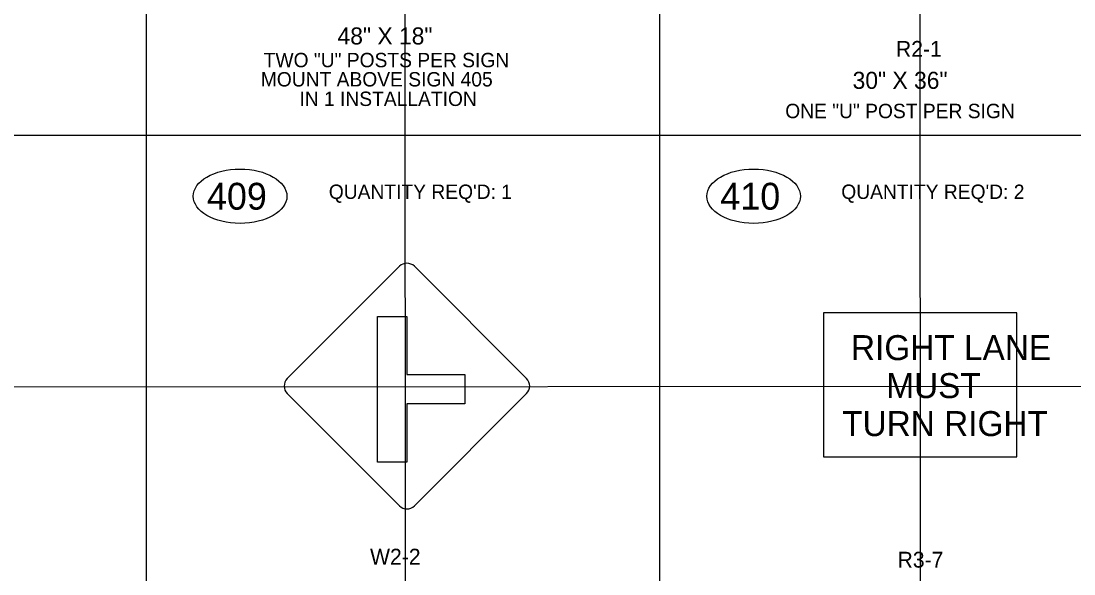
# Model space of a CAD drawing. Extents: x 1977705 to 1981198, y 827296 to 829291.
# Drawn here: x 1979879 to 1980318.3, y 828320.6 to 828551.2 of the extents above; entities that cross this region are included whole.
import ezdxf

# ---------------------------------------------------------------- set-up
doc = ezdxf.new("R2010")
doc.units = 0
doc.layers.add('Level 34', color=7, linetype='Continuous')
doc.layers.add('Level 7', color=7, linetype='Continuous')

msp = doc.modelspace()

# ---------------------------------------------------------------- linework, layer by layer
at = {"layer": 'Level 34'}
for p, q in [((1980039.8, 827664.08), (1980039.2, 828783.26)), ((1980254.68, 827664.19), (1980254.07, 828783.37)), ((1981001.97, 828399.12), (1979481.32, 828398.3))]:
    msp.add_line(p, q, dxfattribs=at)
at = {"layer": 'Level 7'}
for p, q in [((1980027.74, 828428.04), (1980039.89, 828428.04)), ((1980027.74, 828367.29), (1980027.74, 828428.04)), ((1980039.89, 828428.04), (1980039.89, 828403.74)), ((1980039.89, 828403.74), (1980064.19, 828403.74)), ((1980064.19, 828403.74), (1980064.19, 828391.59)), ((1980089.94, 828395.88), (1980043.1, 828349.04)), ((1980064.19, 828391.59), (1980039.89, 828391.59)), ((1980039.89, 828391.59), (1980039.89, 828367.29)), ((1980039.89, 828367.29), (1980027.74, 828367.29))]:
    msp.add_line(p, q, dxfattribs=at)
for points in [[(1979931.19, 828713.79), (1979931.19, 827664.02)], [(1980145.44, 828713.91), (1980145.44, 827664.13)], [(1979502.24, 828503.56), (1980814.64, 828503.56)], [(1979990.06, 828402.07), (1980036.91, 828448.92)], [(1980043.1, 828448.92), (1980089.94, 828402.07)], [(1980036.91, 828349.04), (1979990.06, 828395.88)]]:
    msp.add_lwpolyline(points, dxfattribs=at)
msp.add_lwpolyline([(1980213.78, 828429.46), (1980213.78, 828369.48), (1980294.5, 828369.48), (1980294.5, 828429.46)], close=True, dxfattribs=at)
for centre, start, end in [((1980040, 828445.82), 89.9935, 135), ((1980040, 828445.82), 44.987, 89.9935), ((1979993.16, 828398.98), 135, 225), ((1980086.85, 828398.98), 315, 45), ((1980040, 828352.13), 225, 270), ((1980040, 828352.13), 270, 315)]:
    msp.add_arc(centre, 4.38, start, end, dxfattribs=at)
for centre in [(1979970.39, 828478.14), (1980184.64, 828478.14)]:
    msp.add_ellipse(centre, major_axis=(-19.54, 0), ratio=0.580127, dxfattribs=at)

# ---------------------------------------------------------------- texts
for s, height, p in [('48" X 18"', 7.125, (1980011.05, 828541.42)), ('R2-1', 6.6, (1980244.02, 828536.28)), ('TWO "U" POSTS PER SIGN', 6, (1979980.24, 828531.93)), ('MOUNT ABOVE SIGN 405 ', 6, (1979979.03, 828523.91)), ('30" X 36"', 7.125, (1980225.95, 828522.92)), ('IN 1 INSTALLATION', 6, (1979995.14, 828515.78)), ('ONE "U" POST PER SIGN', 6, (1980197.84, 828510.69)), ("QUANTITY REQ'D: 1", 6, (1980007.4, 828477.01)), ("QUANTITY REQ'D: 2", 6, (1980221.22, 828477.01)), ('W2-2', 6.6, (1980024.61, 828324.54)), ('R3-7', 6.6, (1980244.69, 828323.26))]:
    msp.add_text(s, height=height, dxfattribs=at).set_placement(p)
for s, height, rotation, p in [('409', 11.202, 359.9962, (1979956.57, 828472.54)), ('410', 11.202, 359.9962, (1980170.76, 828472.54)), ('RIGHT LANE', 10.407, 360, (1980225.27, 828409.8)), ('MUST', 10.407, 360, (1980239.99, 828393.96)), ('TURN RIGHT', 10.407, 360, (1980221.61, 828378.12))]:
    msp.add_text(s, height=height, rotation=rotation, dxfattribs=at).set_placement(p)

doc.saveas('drawing.dxf')
